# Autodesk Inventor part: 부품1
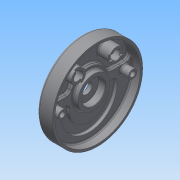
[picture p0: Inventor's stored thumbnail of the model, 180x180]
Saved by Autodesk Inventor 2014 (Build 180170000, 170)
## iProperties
Created: 2015-04
Part Number: 부품1
Material: 일반
Document SubType Name: Modeling
Designer: net
Density: 1 g/cm^3
Appearance: 기본값
Author: net
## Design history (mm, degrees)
sketch "스케치1"
  geometry: C1 r 95 at (0, 0); 1 further point
  constraints: 1 centre point, 1 coincident
  dimensions: "d0" = 190 diameter of C1
extrude "돌출1" new body sketch "스케치1" distance "d1" = 32; taper "d2" = 0 deg
sketch "스케치2"
  geometry: C1 r 95 at (0, 0) reference; C2 r 90 at (0, 0)
  constraints: 1 centre point, 1 coincident
  dimensions: "d3" = 180 diameter of C2
extrude "돌출2" cut sketch "스케치2" distance "d4" = 18; taper "d5" = 0 deg
sketch "스케치3"
  geometry: L1 (0, 0)-(-95, 0); L2 (-47.117, 12)-(-76.916, 12); L3 (47.117, 12)-(76.916, 12); C1 r 90 at (0, 0) reference; C2 r 90 at (0, 0) reference; A1 r 42 centre (0, 0) between (38.056, 17.769) and (-38.056, 17.769); A2 r 10 centre (-47.117, 22) between (-47.117, 12) and (-38.056, 17.769); A3 r 10 centre (-76.916, 22) between (-86.53, 24.75) and (-76.916, 12); A4 r 90 centre (0, 0) between (86.53, 24.75) and (-90, 0); A5 r 10 centre (47.117, 22) between (38.056, 17.769) and (47.117, 12); A6 r 10 centre (76.916, 22) between (76.916, 12) and (86.53, 24.75)
  constraints: 13 point on circle, 8 tangent, 6 centre point, 6 end point, 4 horizontal alignment, 3 equal radius, 2 coincident, 1 collinear, 1 horizontal, 1 point on line, 1 other
  dimensions: "d7" = 84 diameter of A1; "d8" = 20 diameter of A2; "d10" = 12 distance between parallel lines of L1 L2
extrude "돌출3" cut sketch "스케치3" distance "d11" = 7; taper "d12" = 0 deg
sketch "스케치4"
  geometry: C1 r 35 at (0, 0); A1 r 90 centre (0, 0) between (-86.53, 24.75) and (86.53, 24.75) reference
  constraints: 1 centre point, 1 coincident
  dimensions: "d13" = 70 diameter of C1
extrude "돌출4" join sketch "스케치4" distance "d14" = 10; taper "d15" = -10 deg
hole "구멍1" diameter "d18" = 50; stored, may be unused: countersink angle "d22" = 90 deg, drill point angle "d24" = 0 deg; dims "d16" = 10, "d17" = 10, "d19" = 6, "d20" = 4, "d21" = 2, "d23" = 15
hole "구멍2" diameter "d27" = 23; stored, may be unused: countersink angle "d31" = 90 deg, drill point angle "d33" = 0 deg; dims "d25" = 10, "d26" = 10, "d28" = 6, "d29" = 4, "d30" = 2, "d32" = 15
sketch "스케치5"
  geometry: L1 (-47.117, 12)-(-76.916, 12) reference; L2 (-74, 0)-(74, 0); C1 r 35 at (0, 0) reference; C2 r 9 at (-74, 0); C3 r 9 at (74, 0); 1 further point
  constraints: 2 centre point, 2 end point, 2 horizontal alignment, 1 coincident, 1 equal radius, 1 midpoint, 1 parallel
  dimensions: "d34" = 18 diameter of C2; "d35" = 148 distance of L2.end L2.start
extrude "돌출5" join sketch "스케치5" distance "d36" = 18; taper "d37" = 0 deg
sketch "스케치6"
  geometry: L1 (76.916, 12)-(47.117, 12) reference; L2 (-40, 52)-(40, 52); C1 r 15 at (-40, 52); C2 r 15 at (40, 52); A1 r 42 centre (0, 0) between (38.056, 17.769) and (-38.056, 17.769) reference; 1 further point
  constraints: 2 centre point, 2 end point, 1 equal radius, 1 horizontal alignment, 1 midpoint, 1 parallel, 1 vertical alignment
  dimensions: "d38" = 30 diameter of C1; "d39" = 52 vertical distance of A1.centre L2.start; "d40" = 80 distance of L2.end L2.start
extrude "돌출6" join sketch "스케치6" distance "d41" = 25; taper "d42" = 0 deg
hole "구멍3" diameter "d45" = 20; stored, may be unused: countersink angle "d49" = 90 deg, drill point angle "d51" = 0 deg; dims "d43" = 10, "d44" = 10, "d46" = 6, "d47" = 4, "d48" = 2, "d50" = 15
hole "구멍4" diameter "d54" = 20; stored, may be unused: countersink angle "d58" = 90 deg, drill point angle "d60" = 0 deg; dims "d52" = 10, "d53" = 10, "d55" = 6, "d56" = 4, "d57" = 2, "d59" = 15
sketch "스케치7"
  geometry: L1 (-6, 17.523)-(-6, -18.685); L2 (6, 17.523)-(6, -18.685); L3 (-6, 17.523)-(6, 17.523); L4 (-6, -18.685)-(6, -18.685); C1 r 10 at (0, 0) reference; 2 further points
  constraints: 8 end point, 1 midpoint, 1 parallel, 1 perpendicular, 1 vertical, 1 vertical alignment
  dimensions: "d62" = 12 distance of L1.start L2.start; "d63" = 69.52289 distance from line of point (40, -52) L3; "d64" = 36.20794 distance from line of L2.end L3; "d65" = 36.20794 distance from line of L1.end L3
extrude "돌출7" cut sketch "스케치7" distance "d66" = 3; taper "d67" = 0 deg
sketch "스케치8"
  geometry: L1 (-19.523, 6)-(19.523, 6); L2 (19.523, 6)-(19.523, -6); L3 (19.523, -6)-(-19.523, -6); L4 (-19.523, -6)-(-19.523, 6); L5 (-19.523, 6)-(19.523, -6); L6 (19.523, 6)-(-19.523, -6); C1 r 15 at (0, 0) reference; 1 further point
  constraints: 12 end point, 2 midpoint, 2 parallel, 1 horizontal, 1 perpendicular
  dimensions: "d68" = 12 distance of L1.end L2.end; "d69" = 72.9166 deg angle of L5 L2
extrude "돌출8" cut sketch "스케치8" distance "d70" = 3; taper "d71" = 0 deg
hole "구멍5" diameter "d74" = 11; stored, may be unused: countersink angle "d78" = 90 deg, drill point angle "d80" = 0 deg; dims "d72" = 10, "d73" = 10, "d75" = 6, "d76" = 18, "d77" = 11, "d79" = 117
hole "구멍6" diameter "d83" = 11; stored, may be unused: countersink angle "d87" = 90 deg, drill point angle "d89" = 0 deg; dims "d81" = 10, "d82" = 10, "d84" = 6, "d85" = 18, "d86" = 11, "d88" = 117
fillet "모깎기1" dims "d90" = 0.3
chamfer "모따기1" distance "d91" = 1; stored, may be unused: second distance "d92" = 2, angle "d93" = 45 deg
chamfer "모따기2" distance "d94" = 1; stored, may be unused: second distance "d95" = 2, angle "d96" = 45 deg
sketch "스케치9"
  geometry: L1 (-47.117, 12)-(-76.916, 12) reference; L2 (0, 0)-(0, -19); L3 (41, -19)-(59, -19); L4 (0, -19)-(-29.394, -19); L5 (-41, -19)-(-59, -19); L6 (-58.788, -14)-(-40.694, -14); L7 (40.694, -14)-(58.788, -14); C1 r 9 at (-49.741, -14); C2 r 9 at (49.741, -14); A1 r 90 centre (0, 0) between (-86.53, 24.75) and (86.53, 24.75) reference; A2 r 59 centre (0, -19) between (-58.788, -14) and (58.788, -14); A3 r 41 centre (0, -19) between (-40.694, -14) and (40.694, -14); 1 further point
  constraints: 12 end point, 8 point on circle, 4 centre point, 3 perpendicular, 2 coincident, 2 collinear, 2 horizontal alignment, 2 midpoint, 2 parallel, 2 other
  dimensions: "d97" = 19 distance of L2.start L2.end; "d98" = 118 diameter of A2; "d99" = 82 diameter of A3; "d103" = 5 distance between parallel lines of L5 L6; "d104" = 18 diameter of C1; "d105" = 5 distance between parallel lines of L3 L7; "d106" = 18 diameter of C2
extrude "돌출9" cut sketch "스케치9" distance "d107" = 7; taper "d108" = 0 deg
fillet "모깎기2" dims "d109" = 3
fillet "모깎기3" dims "d110" = 3
fillet "모깎기4" dims "d111" = 3
fillet "모깎기5" dims "d112" = 3
fillet "모깎기6" dims "d113" = 3
fillet "모깎기8" dims "d115" = 3
fillet "모깎기9" dims "d116" = 5
fillet "모깎기10" dims "d117" = 1
node "솔리드1"
